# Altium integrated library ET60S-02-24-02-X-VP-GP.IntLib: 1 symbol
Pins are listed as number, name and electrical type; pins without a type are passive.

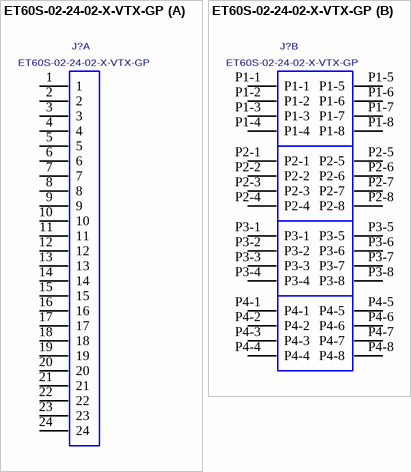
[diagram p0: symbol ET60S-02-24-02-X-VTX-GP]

## ET60S-02-24-02-X-VTX-GP
designator J?
VERTICAL SOCKET ET60 POWER ASSEMBLY.; MANUFACTURER: SAMTEC
footprint ET60S-02-24-02-X-VP-GP
part A pins: 1, 2, 3, 4, 5, 6, 7, 8, 9, 10, 11, 12, 13, 14, 15, 16, 17, 18, 19, 20, 21, 22, 23, 24
part B pins: P1-1, P1-2, P1-3, P1-4, P1-5, P1-6, P1-7, P1-8, P2-1, P2-2, P2-3, P2-4, P2-5, P2-6, P2-7, P2-8, P3-1, P3-2, P3-3, P3-4, P3-5, P3-6, P3-7, P3-8, P4-1, P4-2, P4-3, P4-4, P4-5, P4-6, P4-7, P4-8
